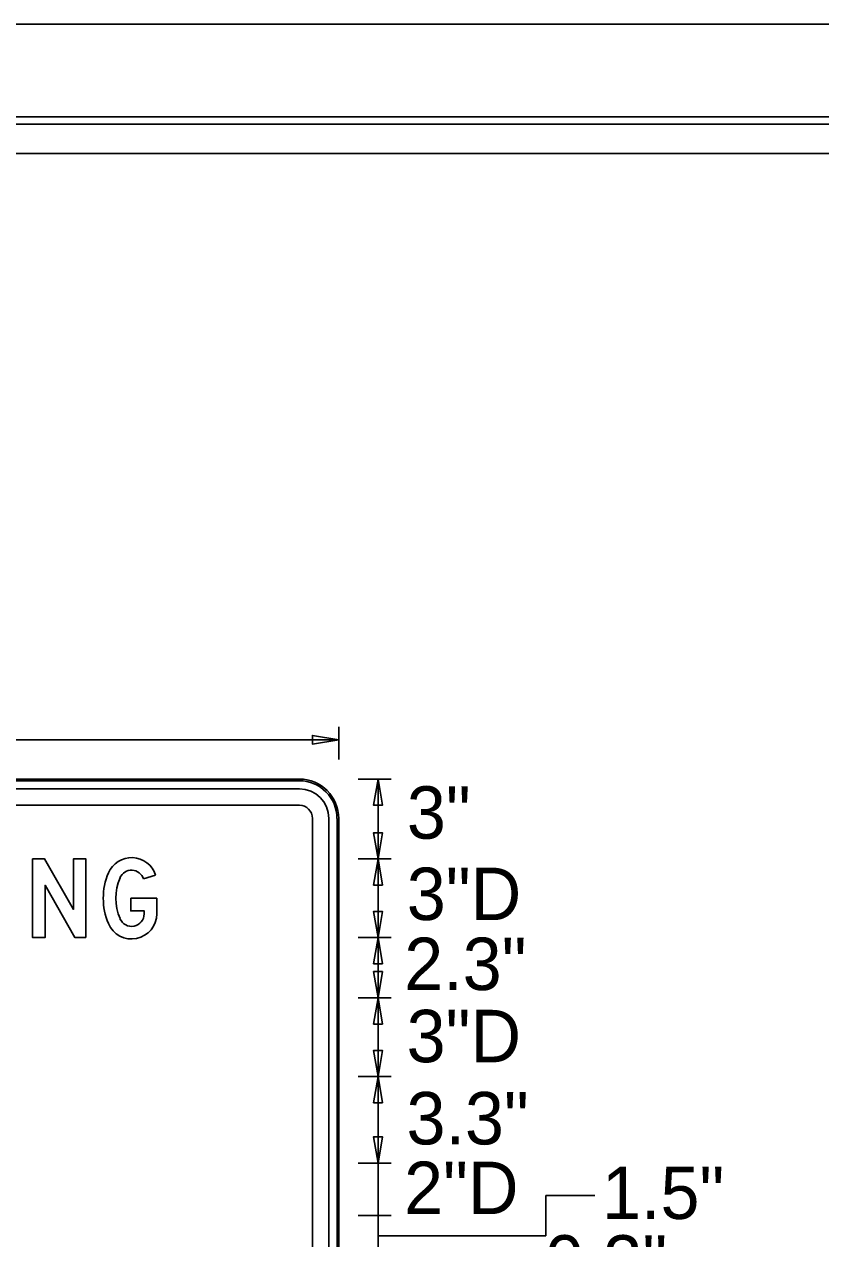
# Model space of a CAD drawing. Extents: x 17890071 to 17890754, y 17897628 to 17897992.
# Drawn here: x 17890204.12 to 17890212.56, y 17897857.62 to 17897870.5 of the extents above; entities that cross this region are included whole.
import ezdxf

# ---------------------------------------------------------------- set-up
doc = ezdxf.new("R2010")
doc.units = 0
for name, color, linetype in [('Default', 7, 'Continuous'), ('GSBWFill', 7, 'Continuous'), ('GSColorFill', 7, 'Continuous'), ('GSDims', 7, 'Continuous'), ('GSOutline', 7, 'Continuous'), ('PlotBorder_dp', 7, 'Continuous'), ('SheetBorder_dp', 7, 'Continuous'), ('SheetLinesMisc2_dp', 7, 'Continuous')]:
    doc.layers.add(name, color=color, linetype=linetype)

msp = doc.modelspace()

# ---------------------------------------------------------------- linework, layer by layer
at = {"layer": 'Default'}
for p, q in [((17890209.651, 17897858.081), (17890209.651, 17897857.657)), ((17890209.651, 17897858.081), (17890210.171, 17897858.081)), ((17890207.871, 17897857.657), (17890209.651, 17897857.657))]:
    msp.add_line(p, q, dxfattribs=at)
at = {"layer": 'GSBWFill'}
for p, q in [((17890207.037, 17897862.496), (17890194.537, 17897862.496)), ((17890207.037, 17897862.391), (17890194.537, 17897862.391)), ((17890194.537, 17897862.218), (17890207.037, 17897862.218)), ((17890207.176, 17897862.079), (17890207.176, 17897851.246)), ((17890207.35, 17897851.246), (17890207.35, 17897862.079)), ((17890207.454, 17897851.246), (17890207.454, 17897862.079)), ((17890205.385, 17897861.438), (17890205.512, 17897861.478))]:
    msp.add_line(p, q, dxfattribs=at)
msp.add_lwpolyline([(17890204.775, 17897860.816), (17890204.775, 17897861.649), (17890204.642, 17897861.649), (17890204.642, 17897861.114), (17890204.336, 17897861.649), (17890204.208, 17897861.649), (17890204.208, 17897860.816), (17890204.342, 17897860.816), (17890204.342, 17897861.37), (17890204.658, 17897860.816)], close=True, dxfattribs=at)
for points in [[(17890205.25, 17897861.233), (17890205.25, 17897861.099), (17890205.392, 17897861.099), (17890205.392, 17897861.068)], [(17890205.525, 17897861.068), (17890205.525, 17897861.233), (17890205.25, 17897861.233)]]:
    msp.add_lwpolyline(points, dxfattribs=at)
for centre, radius, start, end in [((17890207.037, 17897862.079), 0.417, 0, 90), ((17890207.037, 17897862.079), 0.313, 0, 90), ((17890207.037, 17897862.079), 0.139, 0, 90), ((17890205.258, 17897861.397), 0.267, 17.7394, 157.1013), ((17890205.648, 17897861.233), 0.69, 157.1013, 202.8987), ((17890205.648, 17897861.233), 0.556, 157.1013, 202.8987), ((17890205.258, 17897861.397), 0.133, 17.7394, 157.1013), ((17890205.258, 17897861.068), 0.267, 202.8987, 0), ((17890205.258, 17897861.068), 0.133, 202.8987, 0)]:
    msp.add_arc(centre, radius, start, end, dxfattribs=at)
at = {"layer": 'GSColorFill'}
for p, q in [((17890207.037, 17897862.496), (17890194.537, 17897862.496)), ((17890207.037, 17897862.496), (17890194.537, 17897862.496)), ((17890194.537, 17897862.478), (17890207.037, 17897862.478)), ((17890207.037, 17897862.391), (17890194.537, 17897862.391)), ((17890194.537, 17897862.218), (17890207.037, 17897862.218)), ((17890207.176, 17897862.079), (17890207.176, 17897851.246)), ((17890207.35, 17897851.246), (17890207.35, 17897862.079)), ((17890207.437, 17897862.079), (17890207.437, 17897851.246)), ((17890207.454, 17897857.398), (17890207.454, 17897862.079)), ((17890207.454, 17897851.246), (17890207.454, 17897862.079)), ((17890205.385, 17897861.438), (17890205.512, 17897861.478))]:
    msp.add_line(p, q, dxfattribs=at)
msp.add_lwpolyline([(17890204.775, 17897860.816), (17890204.775, 17897861.649), (17890204.642, 17897861.649), (17890204.642, 17897861.114), (17890204.336, 17897861.649), (17890204.208, 17897861.649), (17890204.208, 17897860.816), (17890204.342, 17897860.816), (17890204.342, 17897861.37), (17890204.658, 17897860.816)], close=True, dxfattribs=at)
for points in [[(17890205.25, 17897861.233), (17890205.25, 17897861.099), (17890205.392, 17897861.099), (17890205.392, 17897861.068)], [(17890205.525, 17897861.068), (17890205.525, 17897861.233), (17890205.25, 17897861.233)]]:
    msp.add_lwpolyline(points, dxfattribs=at)
for centre, radius, start, end in [((17890207.037, 17897862.079), 0.417, 0, 90), ((17890207.037, 17897862.079), 0.417, 0, 90), ((17890207.037, 17897862.079), 0.399, 0, 90), ((17890207.037, 17897862.079), 0.313, 0, 90), ((17890207.037, 17897862.079), 0.139, 0, 90), ((17890205.258, 17897861.397), 0.267, 17.7394, 157.1013), ((17890205.648, 17897861.233), 0.69, 157.1013, 202.8987), ((17890205.648, 17897861.233), 0.556, 157.1013, 202.8987), ((17890205.258, 17897861.397), 0.133, 17.7394, 157.1013), ((17890205.258, 17897861.068), 0.267, 202.8987, 0), ((17890205.258, 17897861.068), 0.133, 202.8987, 0)]:
    msp.add_arc(centre, radius, start, end, dxfattribs=at)
at = {"layer": 'GSDims'}
for p, q in [((17890207.454, 17897862.704), (17890207.454, 17897863.051)), ((17890194.121, 17897862.912), (17890207.454, 17897862.912)), ((17890207.662, 17897862.496), (17890208.01, 17897862.496)), ((17890207.871, 17897861.649), (17890207.871, 17897862.496)), ((17890207.662, 17897861.649), (17890208.01, 17897861.649)), ((17890207.662, 17897861.649), (17890208.01, 17897861.649)), ((17890207.871, 17897861.649), (17890207.871, 17897860.816)), ((17890207.662, 17897860.816), (17890208.01, 17897860.816)), ((17890207.662, 17897860.816), (17890208.01, 17897860.816)), ((17890207.871, 17897860.177), (17890207.871, 17897860.816)), ((17890207.662, 17897860.177), (17890208.01, 17897860.177)), ((17890207.662, 17897860.177), (17890208.01, 17897860.177)), ((17890207.871, 17897860.177), (17890207.871, 17897859.344)), ((17890207.662, 17897859.344), (17890208.01, 17897859.344)), ((17890207.662, 17897859.344), (17890208.01, 17897859.344)), ((17890207.871, 17897858.427), (17890207.871, 17897859.344)), ((17890207.662, 17897858.427), (17890208.01, 17897858.427)), ((17890207.662, 17897858.427), (17890208.01, 17897858.427)), ((17890207.871, 17897858.427), (17890207.871, 17897857.871)), ((17890207.662, 17897857.871), (17890208.01, 17897857.871)), ((17890207.662, 17897857.871), (17890208.01, 17897857.871)), ((17890207.871, 17897857.442), (17890207.871, 17897857.871))]:
    msp.add_line(p, q, dxfattribs=at)
for points in [[(17890207.454, 17897862.912), (17890207.176, 17897862.866), (17890207.176, 17897862.959)], [(17890207.871, 17897862.496), (17890207.824, 17897862.218), (17890207.917, 17897862.218)], [(17890207.871, 17897861.649), (17890207.824, 17897861.927), (17890207.917, 17897861.927)], [(17890207.871, 17897861.649), (17890207.824, 17897861.372), (17890207.917, 17897861.372)], [(17890207.871, 17897860.816), (17890207.824, 17897861.094), (17890207.917, 17897861.094)], [(17890207.871, 17897860.816), (17890207.824, 17897860.538), (17890207.917, 17897860.538)], [(17890207.871, 17897860.177), (17890207.824, 17897860.455), (17890207.917, 17897860.455)], [(17890207.871, 17897860.177), (17890207.824, 17897859.899), (17890207.917, 17897859.899)], [(17890207.871, 17897859.344), (17890207.824, 17897859.621), (17890207.917, 17897859.621)], [(17890207.871, 17897859.344), (17890207.824, 17897859.066), (17890207.917, 17897859.066)], [(17890207.871, 17897858.427), (17890207.824, 17897858.705), (17890207.917, 17897858.705)]]:
    msp.add_lwpolyline(points, close=True, dxfattribs=at)
at = {"layer": 'GSOutline'}
for p, q in [((17890207.037, 17897862.496), (17890194.537, 17897862.496)), ((17890207.037, 17897862.391), (17890194.537, 17897862.391)), ((17890207.037, 17897862.218), (17890194.537, 17897862.218)), ((17890207.176, 17897851.246), (17890207.176, 17897862.079)), ((17890207.35, 17897851.246), (17890207.35, 17897862.079)), ((17890207.454, 17897851.246), (17890207.454, 17897862.079)), ((17890205.385, 17897861.438), (17890205.512, 17897861.478))]:
    msp.add_line(p, q, dxfattribs=at)
msp.add_lwpolyline([(17890204.775, 17897860.816), (17890204.775, 17897861.649), (17890204.642, 17897861.649), (17890204.642, 17897861.114), (17890204.336, 17897861.649), (17890204.208, 17897861.649), (17890204.208, 17897860.816), (17890204.342, 17897860.816), (17890204.342, 17897861.37), (17890204.658, 17897860.816)], close=True, dxfattribs=at)
for points in [[(17890205.25, 17897861.233), (17890205.25, 17897861.099), (17890205.392, 17897861.099), (17890205.392, 17897861.068)], [(17890205.525, 17897861.068), (17890205.525, 17897861.233), (17890205.25, 17897861.233)]]:
    msp.add_lwpolyline(points, dxfattribs=at)
for centre, radius, start, end in [((17890207.037, 17897862.079), 0.417, 0, 90), ((17890207.037, 17897862.079), 0.313, 0, 90), ((17890207.037, 17897862.079), 0.139, 0, 90), ((17890205.258, 17897861.397), 0.267, 17.7394, 157.1013), ((17890205.648, 17897861.233), 0.69, 157.1013, 202.8987), ((17890205.648, 17897861.233), 0.556, 157.1013, 202.8987), ((17890205.258, 17897861.397), 0.133, 17.7394, 157.1013), ((17890205.258, 17897861.068), 0.267, 202.8987, 0), ((17890205.258, 17897861.068), 0.133, 202.8987, 0)]:
    msp.add_arc(centre, radius, start, end, dxfattribs=at)
at = {"layer": 'PlotBorder_dp'}
msp.add_lwpolyline([(17890071.13, 17897766.734), (17890232.646, 17897766.734), (17890232.646, 17897870.495), (17890071.13, 17897870.495)], close=True, dxfattribs=at)
at = {"layer": 'SheetBorder_dp'}
msp.add_line((17890076.514, 17897869.516), (17890227.262, 17897869.516), dxfattribs=at)
at = {"layer": 'SheetLinesMisc2_dp'}
for p, q in [((17890076.643, 17897869.435), (17890227.099, 17897869.435)), ((17890175.208, 17897869.124), (17890226.38, 17897869.124))]:
    msp.add_line(p, q, dxfattribs=at)

# ---------------------------------------------------------------- texts
at = {"layer": 'GSDims'}
for s, p in [('3"', (17890208.177, 17897861.864)), ('3"D', (17890208.176, 17897861.002)), ('2.3"', (17890208.149, 17897860.26)), ('3"D', (17890208.174, 17897859.495)), ('3.3"', (17890208.173, 17897858.624)), ('2"D', (17890208.147, 17897857.886)), ('1.5"', (17890210.246, 17897857.834)), ('0.3"', (17890209.641, 17897857.106))]:
    msp.add_text(s, height=0.5556, dxfattribs=at).set_placement(p)

doc.saveas('drawing.dxf')
